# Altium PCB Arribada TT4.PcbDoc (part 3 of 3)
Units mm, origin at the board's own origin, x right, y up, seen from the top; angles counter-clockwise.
Board outline 56 x 35 mm, 6 copper layers (Top Layer, L2GND, L3, L4, L5GND, Bottom Layer), stack 0.865 mm thick; 99 components, 88 nets, 417 pads, 769 vias.
Unrouted connection lines stored in the file: 31.
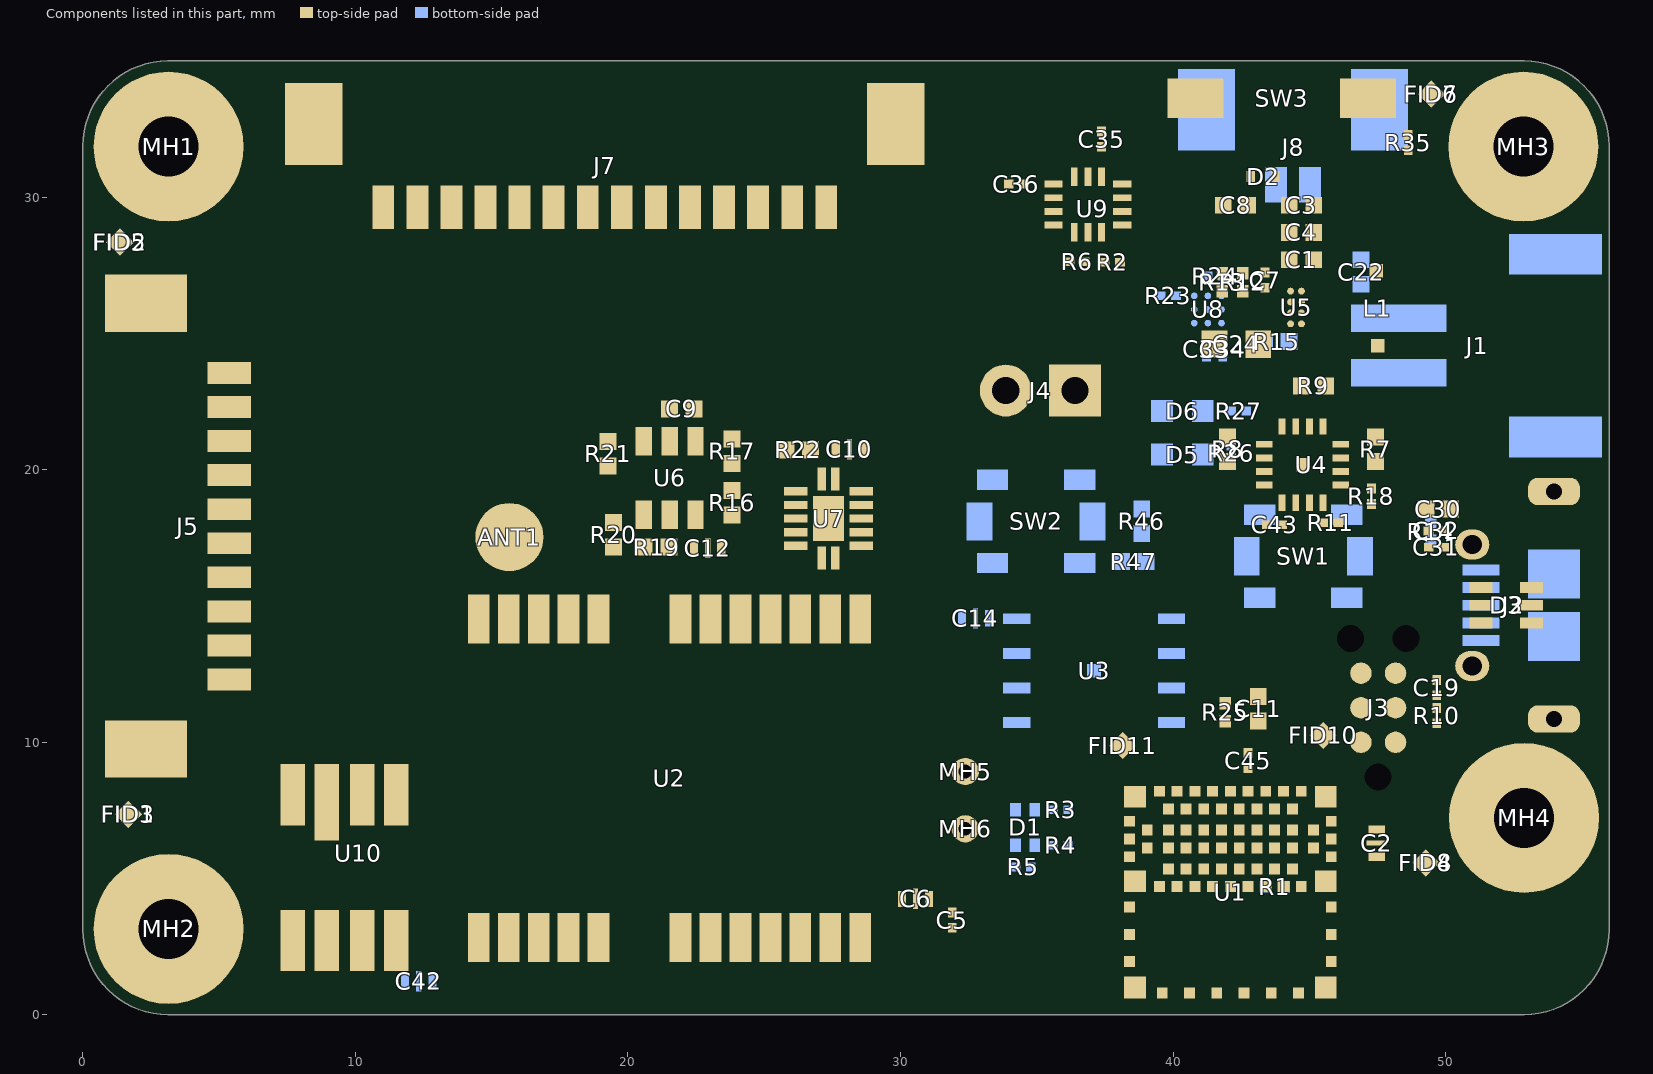
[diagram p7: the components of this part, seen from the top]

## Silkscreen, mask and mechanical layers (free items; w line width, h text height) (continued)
Drill Drawing:
  circle w0.254: c-82.719,165.582 r0.508
  circle w0.254: c-82.719,165.582 r0.847
  circle w0.254: c-82.719,142.722 r0.847
  lines w0.254: -83.566,130.445 -83.566,130.868 -83.142,131.292 -83.566,131.715 -83.566,132.138 -83.142,132.138 -82.719,131.715 -82.296,132.138 -81.872,132.138 -81.872,131.715 -82.296,131.292 -81.872,130.868 -81.872,130.445 -82.296,130.445 -82.719,130.868 -83.142,130.445 -83.566,130.445 ; -83.566,135.102 -82.719,134.255 -81.872,135.102 -82.719,135.948 -83.566,135.102 ; -83.566,138.065 -82.719,138.488 -81.872,138.065 -82.296,138.912 -81.872,139.758 -82.719,139.335 -83.566,139.758 -83.142,138.912 -83.566,138.065 ; -83.566,145.685 -81.872,145.685 -81.872,147.378 -83.566,147.378 -83.566,145.685 ; -83.566,149.918 -83.142,149.918 -83.142,149.495 -82.296,149.495 -82.296,149.918 -81.872,149.918 -81.872,150.765 -82.296,150.765 -82.296,151.188 -83.142,151.188 -83.142,150.765 -83.566,150.765 -83.566,149.918 ; -83.566,153.728 -83.142,153.728 -82.719,153.305 -82.296,153.728 -81.872,153.728 -82.296,154.152 -81.872,154.575 -82.296,154.575 -82.719,154.998 -83.142,154.575 -83.566,154.575 -83.142,154.152 -83.566,153.728 ; -83.566,158.808 -81.872,158.808 -82.719,157.115 -83.566,158.808 ; -83.566,160.925 -81.872,160.925 -81.872,162.618 -83.566,162.618 -83.566,160.925 ; -83.227,161.264 -82.211,161.264 -82.211,162.28 -83.227,162.28 -83.227,161.264
  lines w0.381: -85.085,129.302 136.088,129.302 ; -85.085,167.402 136.088,167.402 ; -71.092,125.492 -71.092,171.212 ; -55.856,125.492 -55.856,171.212 ; -27.924,125.492 -27.924,171.212 ; -15.075,125.492 -15.075,171.212 ; 3.563,125.492 3.563,171.212 ; 41.652,125.492 41.652,171.212 ; 56.634,125.492 56.634,171.212 ; 84.312,125.492 84.312,171.212 ; 113.26,125.492 113.26,171.212 ; -85.085,125.492 136.088,125.492 136.088,171.212 -85.085,171.212 -85.085,125.492
  text "Symbol" at -82.799,168.545 h1.83
  text "Count" at -69.949,168.545 h1.83
  text "Hole Size" at -54.713,168.545 h1.83
  text "Plated" at -26.781,168.545 h1.83
  text "Hole Type" at -13.932,168.545 h1.83
  text "Drill Layer Pair" at 4.706,168.545 h1.83
  text "Via/Pad" at 42.795,168.545 h1.83
  text "Pad Shape" at 57.777,168.545 h1.83
  text "Template" at 85.455,168.545 h1.83
  text "Description" at 114.403,168.545 h1.83
  text "50" at -69.949,164.735 h1.52
  text "0.100mm (3.94mil)" at -54.713,164.735 h1.52
  text "PTH" at -26.781,164.735 h1.52
  text "Round" at -13.932,164.735 h1.52
  text "(Mixed)" at 4.706,164.735 h1.52
  text "Via" at 42.795,164.735 h1.52
  text "Rounded" at 57.777,164.735 h1.52
  text "(Mixed)" at 85.455,164.735 h1.52
  text "48" at -69.949,160.925 h1.52
  text "0.125mm (4.92mil)" at -54.713,160.925 h1.52
  text "PTH" at -26.781,160.925 h1.52
  text "Round" at -13.932,160.925 h1.52
  text "(Mixed)" at 4.706,160.925 h1.52
  text "Via" at 42.795,160.925 h1.52
  text "Rounded" at 57.777,160.925 h1.52
  text "v25h12" at 85.455,160.925 h1.52
  text "22" at -69.949,157.115 h1.52
  text "0.150mm (5.91mil)" at -54.713,157.115 h1.52
  text "PTH" at -26.781,157.115 h1.52
  text "Round" at -13.932,157.115 h1.52
  text "L3 - L4" at 4.706,157.115 h1.52
  text "Via" at 42.795,157.115 h1.52
  text "Rounded" at 57.777,157.115 h1.52
  text "v30h15" at 85.455,157.115 h1.52
  text "648" at -69.949,153.305 h1.52
  text "0.200mm (7.87mil)" at -54.713,153.305 h1.52
  text "PTH" at -26.781,153.305 h1.52
  text "Round" at -13.932,153.305 h1.52
  text "Top Layer - Bottom Layer" at 4.706,153.305 h1.52
  text "Via" at 42.795,153.305 h1.52
  text "Rounded" at 57.777,153.305 h1.52
  text "(Mixed)" at 85.455,153.305 h1.52
  text "2" at -69.949,149.495 h1.52
  text "0.500mm (19.69mil)" at -54.713,149.495 h1.52
  text "PTH" at -26.781,149.495 h1.52
  text "Round" at -13.932,149.495 h1.52
  text "Top Layer - Bottom Layer" at 4.706,149.495 h1.52
  text "Pad" at 42.795,149.495 h1.52
  text "Rounded" at 57.777,149.495 h1.52
  text "c100h50" at 85.455,149.495 h1.52
  text "2" at -69.949,145.685 h1.52
  text "0.600mm (23.62mil)" at -54.713,145.685 h1.52
  text "PTH" at -26.781,145.685 h1.52
  text "Slot" at -13.932,145.685 h1.52
  text "Top Layer - Bottom Layer" at 4.706,145.685 h1.52
  text "Pad" at 42.795,145.685 h1.52
  text "Rounded Rectangle" at 57.777,145.685 h1.52
  text "r100_190h60_130r70" at 85.455,145.685 h1.52
  text "2" at -69.949,141.875 h1.52
  text "0.700mm (27.56mil)" at -54.713,141.875 h1.52
  text "PTH" at -26.781,141.875 h1.52
  text "Slot" at -13.932,141.875 h1.52
  text "Top Layer - Bottom Layer" at 4.706,141.875 h1.52
  text "Pad" at 42.795,141.875 h1.52
  text "Rounded" at 57.777,141.875 h1.52
  text "r110_125h70_85r100" at 85.455,141.875 h1.52
  text "3" at -69.949,138.065 h1.52
  text "0.991mm (39.02mil)" at -54.713,138.065 h1.52
  text "NPTH" at -26.781,138.065 h1.52
  text "Round" at -13.932,138.065 h1.52
  text "Top Layer - Bottom Layer" at 4.706,138.065 h1.52
  text "Pad" at 42.795,138.065 h1.52
  text "Rounded" at 57.777,138.065 h1.52
  text "c65hn99" at 85.455,138.065 h1.52
  text "3" at -69.949,134.255 h1.52
  text "1.000mm (39.37mil)" at -54.713,134.255 h1.52
  text "PTH" at -26.781,134.255 h1.52
  text "Round" at -13.932,134.255 h1.52
  text "Top Layer - Bottom Layer" at 4.706,134.255 h1.52
  text "(Mixed)" at 42.795,134.255 h1.52
  text "(Mixed)" at 57.777,134.255 h1.52
  text "(Mixed)" at 85.455,134.255 h1.52
  text "4" at -69.949,130.445 h1.52
  text "2.200mm (86.61mil)" at -54.713,130.445 h1.52
  text "PTH" at -26.781,130.445 h1.52
  text "Round" at -13.932,130.445 h1.52
  text "Top Layer - Bottom Layer" at 4.706,130.445 h1.52
  text "Pad" at 42.795,130.445 h1.52
  text "Rounded" at 57.777,130.445 h1.52
  text "c550h220" at 85.455,130.445 h1.52
  text "784 Total" at -69.949,126.635 h1.52
  text "Slot definitions :" at -82.799,122.953 h1.52
  text "Routed Path Length" at -56.568,122.953 h1.52
  text "= Calculated from tool start centre position to tool end centre position." at -28.56,122.953 h1.52
  text "Hole Length" at -56.568,120.413 h1.52
  text "= Routed Path Length + Tool Size = Slot length as defined in the PCB layout" at -38.971,120.413 h1.52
